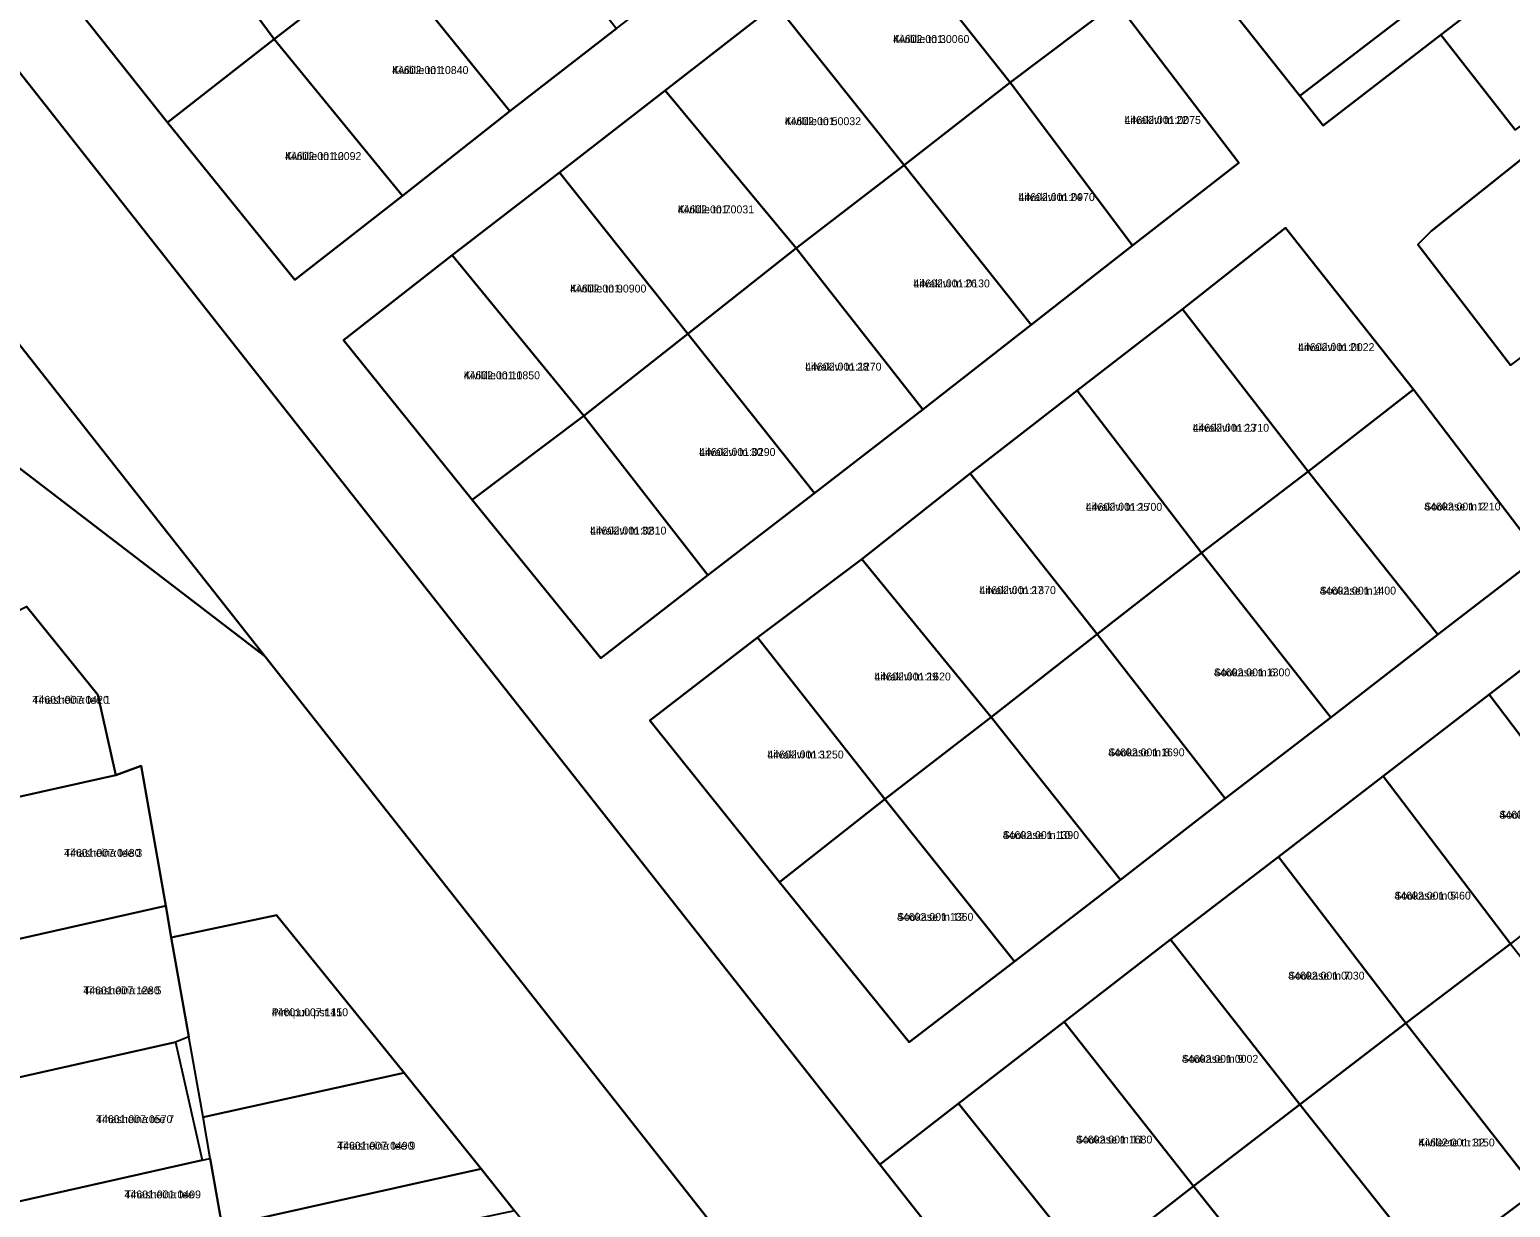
# Model space of a CAD drawing. Extents: x 551843 to 558501, y 6589003 to 6595718.
# Drawn here: x 554097.3 to 554378.5, y 6593574.5 to 6593798.2 of the extents above; entities that cross this region are included whole.
import ezdxf

# ---------------------------------------------------------------- set-up
doc = ezdxf.new("R2010")
doc.units = 0
for name, color, linetype in [('L_AADRESS', 7, 'Continuous'), ('PIIR', 7, 'Continuous'), ('TUNNUS', 7, 'Continuous')]:
    doc.layers.add(name, color=color, linetype=linetype)

msp = doc.modelspace()

# ---------------------------------------------------------------- linework, layer by layer
at = {"layer": 'PIIR'}
for points in [[(554441.09, 6593299.31), (554261.19, 6593527.78), (554141.98, 6593679.18), (554122.61, 6593703.78), (554013.74, 6593842.05), (553788.87, 6594127.63), (553766.28, 6594156.32), (553814.68, 6594146.58), (553836.64, 6594118.69), (553980.12, 6593936.47), (554062.14, 6593832.31), (554258.75, 6593582.61), (554309.59, 6593518.04), (554467.93, 6593316.95)], [(553918.7, 6593842.58), (554046.25, 6593756.59), (554079.11, 6593727.32), (554141.98, 6593679.18), (554261.19, 6593527.78), (554441.09, 6593299.31)], [(554013.74, 6593842.05), (554122.61, 6593703.78), (554141.98, 6593679.18), (554079.11, 6593727.32), (554046.25, 6593756.59), (553918.7, 6593842.58)], [(554393.47, 6593686.49), (554374.48, 6593671.9), (554354.38, 6593656.38), (554334.49, 6593641.06), (554313.97, 6593625.33), (554293.76, 6593609.72), (554273.69, 6593594.18), (554258.75, 6593582.61), (554062.14, 6593832.31)], [(554398.26, 6593822.53), (554365.34, 6593797.2), (554342.99, 6593780), (554338.55, 6593785.6), (554361, 6593802.86), (554393.62, 6593827.94)], [(554326.33, 6593801), (554338.55, 6593785.6), (554342.99, 6593780), (554365.34, 6593797.2), (554379.46, 6593779.15)], [(554382.56, 6593775.13), (554363.49, 6593759.93), (554360.94, 6593757.39), (554378.58, 6593734.45)], [(554370.87, 6593348.86), (554359.29, 6593363.51), (554355.96, 6593363.33), (554355.52, 6593367.92), (554338.59, 6593388.74), (554314.55, 6593387.45), (554313.51, 6593405.27), (554307.37, 6593427.52), (554277.53, 6593464.41), (554260.2, 6593485.51), (554255.79, 6593491.05), (554245.13, 6593504.82), (554217.11, 6593539.51), (554189.38, 6593573.83), (554183.04, 6593581.77), (554168.4, 6593600.04), (554144.19, 6593629.98), (554124.2, 6593625.76), (554123.15, 6593631.73), (554118.48, 6593658.32), (554113.64, 6593656.6), (554110.23, 6593671.81), (554096.69, 6593688.65)], [(554467.93, 6593316.95), (554309.59, 6593518.04), (554258.75, 6593582.61), (554273.69, 6593594.18), (554298.61, 6593563.13), (554323.57, 6593532.14), (554343.27, 6593547.24), (554363.47, 6593562.61), (554383.58, 6593577.63)], [(554092.95, 6593575.11), (554130.03, 6593583.41), (554131.6, 6593583.76), (554133.87, 6593570.82), (554183.04, 6593581.77), (554189.38, 6593573.83), (554177.67, 6593571.34), (554156.44, 6593566.58), (554135.34, 6593561.74), (554113.99, 6593556.97), (554095.21, 6593552.75), (554099.27, 6593512.97), (554103.1, 6593472.87), (554096.58, 6593470.92)]]:
    msp.add_lwpolyline(points, dxfattribs=at)
for points in [[(554247.75, 6593876.35), (554223.57, 6593908.42), (554202.89, 6593892.39), (554192.77, 6593884.46), (554181.48, 6593875.62), (554160.5, 6593860.04), (554140.08, 6593844.48), (554119.76, 6593828.86), (554098.05, 6593812.64), (554123.45, 6593780.55), (554147.63, 6593750.67), (554168.12, 6593766.66), (554188.5, 6593782.71), (554208.75, 6593798.41), (554229.41, 6593814.22), (554249.27, 6593829.83), (554270.66, 6593846.54)], [(554379.38, 6593847.01), (554393.62, 6593827.94), (554361, 6593802.86), (554338.55, 6593785.6), (554326.33, 6593801), (554346.37, 6593821.81)], [(554164.52, 6593812.44), (554143.76, 6593796.37), (554119.76, 6593828.86), (554140.08, 6593844.48)], [(554303.73, 6593803.37), (554279.52, 6593834.76), (554259.26, 6593818.76), (554238.99, 6593802.96), (554218, 6593786.65), (554197.9, 6593771.05), (554177.57, 6593755.33), (554156.91, 6593739.23), (554181.35, 6593708.87), (554205.75, 6593678.78), (554226.12, 6593694.56), (554246.36, 6593710.17), (554266.91, 6593726.03), (554287.48, 6593742.14), (554306.78, 6593757.18), (554326.95, 6593772.91)], [(554279.52, 6593834.76), (554303.73, 6593803.37), (554283.55, 6593788.18), (554259.26, 6593818.76)], [(554098.05, 6593812.64), (554119.76, 6593828.86), (554143.76, 6593796.37), (554123.45, 6593780.55)], [(554208.75, 6593798.41), (554188.5, 6593782.71), (554164.52, 6593812.44), (554185.13, 6593828.19)], [(554398.26, 6593822.53), (554412.57, 6593803.66), (554379.46, 6593779.15), (554365.34, 6593797.2)], [(554259.26, 6593818.76), (554283.55, 6593788.18), (554263.39, 6593772.47), (554238.99, 6593802.96)], [(554164.52, 6593812.44), (554188.5, 6593782.71), (554168.12, 6593766.66), (554143.76, 6593796.37)], [(554238.99, 6593802.96), (554263.39, 6593772.47), (554242.85, 6593756.69), (554218, 6593786.65)], [(554283.55, 6593788.18), (554303.73, 6593803.37), (554326.95, 6593772.91), (554306.78, 6593757.18)], [(554123.45, 6593780.55), (554143.76, 6593796.37), (554168.12, 6593766.66), (554147.63, 6593750.67)], [(554283.55, 6593788.18), (554306.78, 6593757.18), (554287.48, 6593742.14), (554263.39, 6593772.47)], [(554218, 6593786.65), (554242.85, 6593756.69), (554222.28, 6593740.44), (554197.9, 6593771.05)], [(554394.6, 6593759.73), (554400.84, 6593751.11), (554378.58, 6593734.45), (554360.94, 6593757.39), (554363.49, 6593759.93), (554382.56, 6593775.13)], [(554197.9, 6593771.05), (554222.28, 6593740.44), (554202.54, 6593724.85), (554177.57, 6593755.33)], [(554263.39, 6593772.47), (554287.48, 6593742.14), (554266.91, 6593726.03), (554242.85, 6593756.69)], [(554360.14, 6593729.85), (554335.8, 6593760.53), (554316.27, 6593745.09), (554296.24, 6593729.67), (554275.92, 6593713.87), (554255.36, 6593697.58), (554235.56, 6593682.72), (554215.1, 6593666.98), (554239.7, 6593636.25), (554264.36, 6593605.87), (554284.36, 6593621.19), (554304.5, 6593636.7), (554324.37, 6593652.12), (554344.4, 6593667.55), (554364.74, 6593683.27), (554384.19, 6593698.23)], [(554340.13, 6593714.29), (554316.27, 6593745.09), (554335.8, 6593760.53), (554360.14, 6593729.85)], [(554222.28, 6593740.44), (554242.85, 6593756.69), (554266.91, 6593726.03), (554246.36, 6593710.17)], [(554177.57, 6593755.33), (554202.54, 6593724.85), (554181.35, 6593708.87), (554156.91, 6593739.23)], [(554316.27, 6593745.09), (554340.13, 6593714.29), (554319.88, 6593698.82), (554296.24, 6593729.67)], [(554222.28, 6593740.44), (554246.36, 6593710.17), (554226.12, 6593694.56), (554202.54, 6593724.85)], [(554296.24, 6593729.67), (554319.88, 6593698.82), (554300.05, 6593683.38), (554275.92, 6593713.87)], [(554360.14, 6593729.85), (554384.19, 6593698.23), (554364.74, 6593683.27), (554340.13, 6593714.29)], [(554202.54, 6593724.85), (554226.12, 6593694.56), (554205.75, 6593678.78), (554181.35, 6593708.87)], [(554340.13, 6593714.29), (554364.74, 6593683.27), (554344.4, 6593667.55), (554319.88, 6593698.82)], [(554275.92, 6593713.87), (554300.05, 6593683.38), (554279.94, 6593667.6), (554255.36, 6593697.58)], [(554255.36, 6593697.58), (554279.94, 6593667.6), (554259.7, 6593651.99), (554235.56, 6593682.72)], [(554319.88, 6593698.82), (554344.4, 6593667.55), (554324.37, 6593652.12), (554300.05, 6593683.38)], [(554082.04, 6593681.43), (554096.69, 6593688.65), (554110.23, 6593671.81), (554113.64, 6593656.6), (554085.24, 6593650.25)], [(554393.47, 6593686.49), (554418.61, 6593655.37), (554398.48, 6593640.26), (554374.48, 6593671.9)], [(554300.05, 6593683.38), (554324.37, 6593652.12), (554304.5, 6593636.7), (554279.94, 6593667.6)], [(554235.56, 6593682.72), (554259.7, 6593651.99), (554239.7, 6593636.25), (554215.1, 6593666.98)], [(554374.48, 6593671.9), (554398.48, 6593640.26), (554378.53, 6593624.54), (554354.38, 6593656.38)], [(554279.94, 6593667.6), (554304.5, 6593636.7), (554284.36, 6593621.19), (554259.7, 6593651.99)], [(554087.98, 6593623.81), (554085.24, 6593650.25), (554113.64, 6593656.6), (554118.48, 6593658.32), (554123.15, 6593631.73)], [(554354.38, 6593656.38), (554378.53, 6593624.54), (554358.69, 6593609.46), (554334.49, 6593641.06)], [(554259.7, 6593651.99), (554284.36, 6593621.19), (554264.36, 6593605.87), (554239.7, 6593636.25)], [(554334.49, 6593641.06), (554358.69, 6593609.46), (554338.52, 6593594.03), (554313.97, 6593625.33)], [(554087.98, 6593623.81), (554123.15, 6593631.73), (554124.2, 6593625.76), (554127.52, 6593606.88), (554125, 6593605.85), (554090.58, 6593598.15)], [(554124.2, 6593625.76), (554144.19, 6593629.98), (554148.78, 6593624.3), (554168.4, 6593600.04), (554130.22, 6593591.59), (554127.52, 6593606.88)], [(554313.97, 6593625.33), (554338.52, 6593594.03), (554318.34, 6593578.52), (554293.76, 6593609.72)], [(554378.53, 6593624.54), (554403.33, 6593592.97), (554383.58, 6593577.63), (554358.69, 6593609.46)], [(554298.61, 6593563.13), (554273.69, 6593594.18), (554293.76, 6593609.72), (554318.34, 6593578.52)], [(554358.69, 6593609.46), (554383.58, 6593577.63), (554363.47, 6593562.61), (554338.52, 6593594.03)], [(554090.58, 6593598.15), (554125, 6593605.85), (554130.03, 6593583.41), (554092.95, 6593575.11)], [(554168.4, 6593600.04), (554183.04, 6593581.77), (554133.87, 6593570.82), (554131.6, 6593583.76), (554130.22, 6593591.59)], [(554338.52, 6593594.03), (554363.47, 6593562.61), (554343.27, 6593547.24), (554318.34, 6593578.52)], [(554318.34, 6593578.52), (554343.27, 6593547.24), (554323.57, 6593532.14), (554298.61, 6593563.13)]]:
    msp.add_lwpolyline(points, close=True, dxfattribs=at)

# ---------------------------------------------------------------- texts
at = {"layer": 'L_AADRESS'}
for s, p in [('Kivilille tn 3', (554261.27, 6593795.67)), ('Kivilille tn 10', (554166.13, 6593789.77)), ('Liivakivi tn 22', (554305.25, 6593780.3)), ('Kivilille tn 5', (554240.7, 6593780.06)), ('Kivilille tn 12', (554145.79, 6593773.43)), ('Kivilille tn 7', (554220.38, 6593763.31)), ('Liivakivi tn 24', (554285.09, 6593765.64)), ('Liivakivi tn 26', (554265.16, 6593749.24)), ('Kivilille tn 9', (554199.93, 6593748.27)), ('Liivakivi tn 21', (554338.21, 6593737.14)), ('Liivakivi tn 28', (554244.59, 6593733.43)), ('Kivilille tn 11', (554179.72, 6593731.79)), ('Liivakivi tn 23', (554318.19, 6593721.82)), ('Liivakivi tn 30', (554224.45, 6593717.21)), ('Liivakivi tn 25', (554297.9, 6593706.8)), ('Sookase tn 2', (554362.16, 6593706.86)), ('Liivakivi tn 32', (554203.73, 6593702.29)), ('Liivakivi tn 27', (554277.7, 6593690.97)), ('Sookase tn 4', (554342.31, 6593690.88)), ('Liivakivi tn 29', (554257.75, 6593674.57)), ('Sookase tn 6', (554322.22, 6593675.35)), ('Tihasheina tee 1', (554097.84, 6593670.14)), ('Liivakivi tn 31', (554237.4, 6593659.75)), ('Sookase tn 8', (554302.15, 6593660.16)), ('Sookase tn 3', (554376.43, 6593648.32)), ('Sookase tn 10', (554282.1, 6593644.45)), ('Tihasheina tee 3', (554103.85, 6593641.07)), ('Sookase tn 5', (554356.51, 6593632.94)), ('Sookase tn 12', (554262.03, 6593628.91)), ('Sookase tn 7', (554336.33, 6593617.74)), ('Tihasheina tee 5', (554107.49, 6593614.94)), ('Pirnipuu pst 110', (554143.27, 6593610.79)), ('Sookase tn 9', (554316.14, 6593601.94)), ('Tihasheina tee 7', (554109.91, 6593590.48)), ('Sookase tn 11', (554296.02, 6593586.61)), ('Kivileete tn 32', (554361.05, 6593586.05)), ('Tihasheina tee 9', (554155.71, 6593585.43)), ('Tihasheina tee', (554115.32, 6593576.18))]:
    msp.add_text(s, height=1.5, dxfattribs=at).set_placement(p)
at = {"layer": 'TUNNUS'}
for s, p in [('44602:001:0060', (554261.27, 6593795.67)), ('44602:001:0840', (554166.13, 6593789.77)), ('44602:001:0075', (554305.25, 6593780.3)), ('44602:001:0032', (554240.7, 6593780.06)), ('44602:001:0092', (554145.79, 6593773.43)), ('44602:001:0031', (554220.38, 6593763.31)), ('44602:001:0970', (554285.09, 6593765.64)), ('44602:001:0130', (554265.16, 6593749.24)), ('44602:001:0900', (554199.93, 6593748.27)), ('44602:001:0022', (554338.21, 6593737.14)), ('44602:001:1270', (554244.59, 6593733.43)), ('44602:001:0850', (554179.72, 6593731.79)), ('44602:001:1710', (554318.19, 6593721.82)), ('44602:001:0290', (554224.45, 6593717.21)), ('44602:001:1700', (554297.9, 6593706.8)), ('44602:001:1210', (554362.16, 6593706.86)), ('44602:001:0810', (554203.73, 6593702.29)), ('44602:001:1370', (554277.7, 6593690.97)), ('44602:001:1400', (554342.31, 6593690.88)), ('44602:001:1620', (554257.75, 6593674.57)), ('44602:001:1300', (554322.22, 6593675.35)), ('44601:007:0420', (554097.84, 6593670.14)), ('44602:001:1250', (554237.4, 6593659.75)), ('44602:001:1690', (554302.15, 6593660.16)), ('44602:001:1380', (554376.43, 6593648.32)), ('44602:001:1390', (554282.1, 6593644.45)), ('44601:007:0480', (554103.85, 6593641.07)), ('44602:001:0460', (554356.51, 6593632.94)), ('44602:001:1360', (554262.03, 6593628.91)), ('44602:001:0030', (554336.33, 6593617.74)), ('44601:007:1280', (554107.49, 6593614.94)), ('44601:007:1450', (554143.27, 6593610.79)), ('44602:001:0002', (554316.14, 6593601.94)), ('44601:007:0570', (554109.91, 6593590.48)), ('44602:001:1680', (554296.02, 6593586.61)), ('44601:007:0490', (554155.71, 6593585.43)), ('44602:001:1150', (554361.05, 6593586.05)), ('44601:001:0409', (554115.32, 6593576.18))]:
    msp.add_text(s, height=1.5, dxfattribs=at).set_placement(p)

doc.saveas('drawing.dxf')
